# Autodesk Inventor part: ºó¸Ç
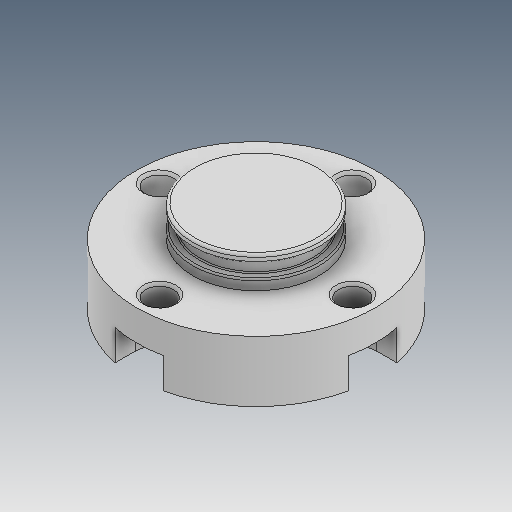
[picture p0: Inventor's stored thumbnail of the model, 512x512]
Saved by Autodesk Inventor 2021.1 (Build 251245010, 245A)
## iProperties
Created: 2015-08
Part Number: ºó¸Ç
Material: Ogólny
Document SubType Name: Modeling
Designer: user
Density: 1 g/cm^3
Appearance: Domyślna
Author: user
Revision Number: ÈÎºÎ
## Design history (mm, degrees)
feature "µ¹½Ç2"
node "Bryła1"
